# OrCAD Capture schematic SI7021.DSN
size B; title: Si7020/7021 postage stamp; rev: 1.0
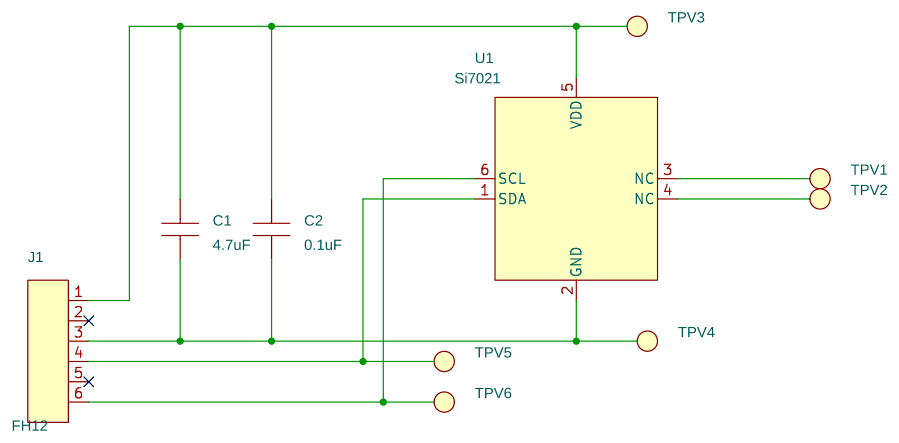
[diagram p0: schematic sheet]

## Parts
C1  4.7uF  [C0603]
C2  0.1uF  [C0402]
J1  FH12  [CONN6N-FPC/FFC-P0.5]
TPV1  TPV  [VIA-TP]
TPV2  TPV  [VIA-TP]
TPV3  TPV  [VIA-TP]
TPV4  TPV  [VIA-TP]
TPV5  TPV  [VIA-TP]
TPV6  TPV  [VIA-TP]
U1  Si7021  [DFN6M3X3P1.0E]

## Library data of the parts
C1 = CAP_NP: CAP, 4.7uF, 6.3V, ±10%, X5R, 0603; Manufacturer: Venkel; ManufacturerPN: C0603X5R6R3-475K; Part_Type: CAP/NP; SiLabsPN: C0603X5R6R3-475K; Tolerance: ±10%; Type: X5R; Voltage: 6.3V; Datasheet: PID_C.pdf
C2 = CAP_NP: CAP, 0.1uF, 10V, ±10%, X7R, 0402; Manufacturer: Venkel; ManufacturerPN: C0402X7R100-104K; Part_Type: CAP/NP; SiLabsPN: C0402X7R100-104K; Tolerance: ±10%; Type: X7R; Voltage: 10V; Datasheet: PID_C.pdf
J1 = CON6: CONN, 6-PIN , FPC/FFC, BOTTOM CONTACT, 0.5MM PITCH, SMD; Manufacturer: HIROSE; ManufacturerPN: FH12-6S-0.5SH(55); Part_Type: CON/MODULAR; SiLabsPN: FH12-6S-0.5SH(55); Datasheet: e58605370.pdf
TPV1-TPV6 = TPV: TESTPOINT Via; Manufacturer: N/A; ManufacturerPN: N/A; Type: PCB Feature
U1 = SI7021: IC, Digital I2C Humidity and Temperature Sensor, ±3% RH, ±0.4°C, DFN6; Manufacturer: SiLabs; ManufacturerPN: Si7021-A-YM1; SiLabsPN: Si7021-A-YM1; Type: Humidity and Temperature; Datasheet: Si7021Rev0 1.pdf

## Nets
N16761461: C1.2 C2.2 J1.1 TPV3.1(Point) U1.5(VDD)
N16761469: J1.4 TPV5.1(Point) U1.1(SDA)
N16761585: J1.6 TPV6.1(Point) U1.6(SCL)
N16761613: C1.1 C2.1 J1.3 TPV4.1(Point) U1.2(GND)
N16764478: TPV1.1(Point) U1.3(NC)
N16764482: TPV2.1(Point) U1.4(NC)

Not connected (* = marked no-connect by the designer): J1 2* 5*
